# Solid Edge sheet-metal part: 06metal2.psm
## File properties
Author: User
Template: Iso Metric Sheet Metal.psm
Last saved by: User
Revision: 5
Application: Solid Edge
Accuracy: 0,990
Material Thickness: 0,25 mm
Bend Radius: 1,00 mm
Relief Width: 1,00 mm
Relief Length: 0,00 mm
Neutral Factor: 0,330
Minimum Arc Length: 0,10 mm
Deviational Tolerance: 0,10 mm
Username: User
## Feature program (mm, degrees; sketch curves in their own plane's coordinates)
base tab "unnamed BaseTab 1"
jog tab "JogTab_4"  OffsetDistance = 0.7501 mm
jog tab "JogTab_5"  OffsetDistance = 0.75 mm
sketch for "unnamed Cutout 1" plane through (2.7023, -5.1071, 0.25) normal (0, 0, 1) x-axis (1, 0, 0)
  circle centre (-0.0077, 0) radius 0.125
extrude "unnamed Cutout 1" cut
mirror "unnamed Mirror 1" of "unnamed Cutout 1" about plane through (0, 0, 0) normal (1, 0, 0)
extrude "unnamed Cutout 2" cut
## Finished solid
Body 1: solid body, 20 faces, 52 edges, 32 vertices.
  Faces by surface: cylinder 10, plane 10
  Edges by curve: line 32, circle 18, curve on surface 2
Bounding box of the edges (mm): 6.000 x 1.250 x 1.000, from (-3, -5.7321, -0.0001) to (3, -4.4821, 1).
Cylindrical faces by radius (mm): R0.125 x2, R0.5 x4, R0.75 x4
Planar faces by outward normal: +x 1, +y 1, +z 3, -x 1, -y 1, -z 3
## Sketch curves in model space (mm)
circle centre (2.6947, -5.1071, 0.25) radius 0.125
line (3, -4.4821, 0) -> (3, -5.7321, 0)
line (3, -5.7321, 0) -> (-3, -5.7321, 0)
line (-3, -5.7321, 0) -> (-3, -4.4821, 0)
line (-3, -4.4821, 0) -> (3, -4.4821, 0)
line (0, 17.1336, 22.4054) -> (0, 17.1336, 34.832)
line (0, 17.1336, 34.832) -> (0, -13.1797, 34.832)
line (0, -13.1797, 34.832) -> (0, -13.1797, 22.4054)
line (0, -13.1797, 22.4054) -> (0, 17.1336, 22.4054)
line (-1.75, -4.4821, 1.75) -> (-1.75, -5.7321, 1.75)
line (1.75, -4.4821, 1.75) -> (1.75, -5.7321, 1.75)
line (3, -4.4821, 1.75) -> (-3, -4.4821, 1.75)
line (-3, -4.4821, 1.75) -> (-3, -5.7321, 1.75)
line (-3, -5.7321, 1.75) -> (3, -5.7321, 1.75)
line (3, -5.7321, 1.75) -> (3, -4.4821, 1.75)
line (1.75, -4.4821, 1) -> (1.75, -5.7321, 1)
line (-1.75, -4.4821, 1) -> (-1.75, -5.7321, 1)
line (-3, -4.4821, 1) -> (-3, -5.7321, 1)
line (-3, -5.7321, 1) -> (3, -5.7321, 1)
line (3, -5.7321, 1) -> (3, -4.4821, 1)
line (3, -4.4821, 1) -> (-3, -4.4821, 1)
line (-1.75, -4.4821, 1) -> (-1.75, -5.7321, 1)
line (1.75, -4.4821, 1) -> (1.75, -5.7321, 1)
line (3, -5.7321, 1) -> (3, -4.4821, 1)
line (3, -4.4821, 1) -> (-3, -4.4821, 1)
line (-3, -4.4821, 1) -> (-3, -5.7321, 1)
line (-3, -5.7321, 1) -> (3, -5.7321, 1)
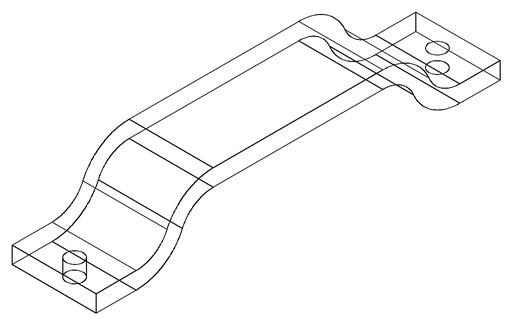
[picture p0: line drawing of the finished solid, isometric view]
